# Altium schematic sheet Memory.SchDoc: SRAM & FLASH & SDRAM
size A4; DocumentNumber: MB1167; Revision: B.1; SheetNumber: 4; SheetTotal: 17; Project: STM327x6G-EVAL
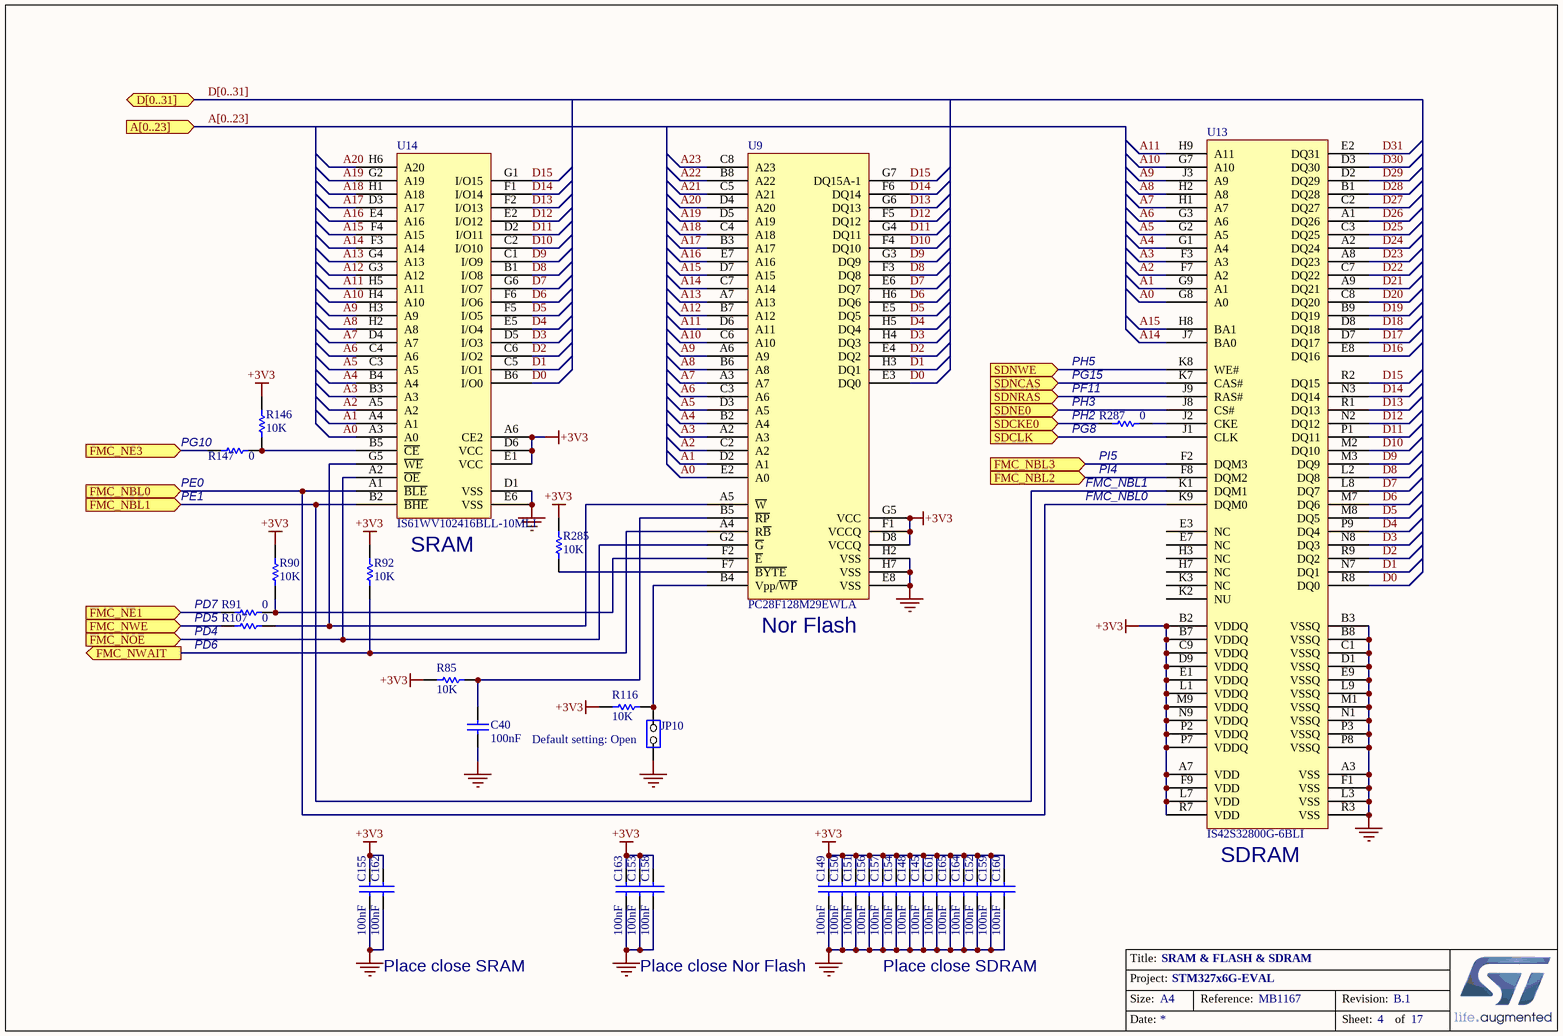
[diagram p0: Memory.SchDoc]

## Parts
C40  100nF  [0603C]
C145  100nF  [0603C]
C148  100nF  [0603C]
C149  100nF  [0603C]
C150  100nF  [0603C]
C151  100nF  [0603C]
C152  100nF  [0603C]
C153  100nF  [0603C]
C154  100nF  [0603C]
C155  100nF  [0603C]
C156  100nF  [0603C]
C157  100nF  [0603C]
C158  100nF  [0603C]
C159  100nF  [0603C]
C160  100nF  [0603C]
C161  100nF  [0603C]
C162  100nF  [0603C]
C163  100nF  [0603C]
C164  100nF  [0603C]
C165  100nF  [0603C]
JP10  (no value)  [SIP2]
R85  10K  [0603R]
R90  10K  [0603R]
R91  0  [0603R]
R92  10K  [0603R]
R107  0  [0603R]
R116  10K  [0603R]
R146  10K  [0603R]
R147  0  [0603R]
R285  10K  [0603R]
R287  0  [0603R]
U9  PC28F128M29EWLA  [FBGA64_1_11X13]
U13  IS42S32800G-6BLI  [FBGA90_0R8_8X13]
U14  IS61WV102416BLL-10MLI  [BGA48_0R75_9X11]

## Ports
A[0..23] (in), D[0..31] (bidir), FMC_NBL0 (in), FMC_NBL1 (in), FMC_NBL2 (in), FMC_NBL3 (in), FMC_NE1 (in), FMC_NE3 (in), FMC_NOE (in), FMC_NWAIT (out), FMC_NWE (in), SDCKE0 (in), SDCLK (in), SDNCAS (in), SDNE0 (in), SDNRAS (in), SDNWE (in)

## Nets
+3V3: C145.1 C148.1 C149.1 C150.1 C151.1 C152.1 C153.1 C154.1 C155.1 C156.1 C157.1 C158.1 C159.1 C160.1 C161.1 C162.1 C163.1 C164.1 C165.1 R85.1 R90.2 R92.2 R116.2 R146.2 R285.2 U9.D8(VCCQ) U9.F1(VCCQ) U9.G5(VCC) U13.A7(VDD) U13.B2(VDDQ) U13.B7(VDDQ) U13.C9(VDDQ) U13.D9(VDDQ) U13.E1(VDDQ) U13.F9(VDD) U13.L1(VDDQ) U13.L7(VDD) U13.M9(VDDQ) U13.N9(VDDQ) U13.P2(VDDQ) U13.P7(VDDQ) U13.R7(VDD) U14.A6(CE2) U14.D6(VCC) U14.E1(VCC)
GND: C40.2 C145.2 C148.2 C149.2 C150.2 C151.2 C152.2 C153.2 C154.2 C155.2 C156.2 C157.2 C158.2 C159.2 C160.2 C161.2 C162.2 C163.2 C164.2 C165.2 JP10.1(COMMON) U9.E8(VSS) U9.H2(VSS) U9.H7(VSS) U13.A3(VSS) U13.B3(VSSQ) U13.B8(VSSQ) U13.C1(VSSQ) U13.D1(VSSQ) U13.E9(VSSQ) U13.F1(VSS) U13.L3(VSS) U13.L9(VSSQ) U13.M1(VSSQ) U13.N1(VSSQ) U13.P3(VSSQ) U13.P8(VSSQ) U13.R3(VSS) U14.D1(VSS) U14.E6(VSS)
A0: U9.E2(A0) U13.G8(A0) U14.A3(A0)
A1: U9.D2(A1) U13.G9(A1) U14.A4(A1)
A2: U9.C2(A2) U13.F7(A2) U14.A5(A2)
A3: U9.A2(A3) U13.F3(A3) U14.B3(A3)
A4: U9.B2(A4) U13.G1(A4) U14.B4(A4)
A5: U9.D3(A5) U13.G2(A5) U14.C3(A5)
A6: U9.C3(A6) U13.G3(A6) U14.C4(A6)
A7: U9.A3(A7) U13.H1(A7) U14.D4(A7)
A8: U9.B6(A8) U13.H2(A8) U14.H2(A8)
A9: U9.A6(A9) U13.J3(A9) U14.H3(A9)
A10: U9.C6(A10) U13.G7(A10) U14.H4(A10)
A11: U9.D6(A11) U13.H9(A11) U14.H5(A11)
A12: U9.B7(A12) U14.G3(A12)
A13: U9.A7(A13) U14.G4(A13)
A14: U9.C7(A14) U13.J7(BA0) U14.F3(A14)
A15: U9.D7(A15) U13.H8(BA1) U14.F4(A15)
A16: U9.E7(A16) U14.E4(A16)
A17: U9.B3(A17) U14.D3(A17)
A18: U9.C4(A18) U14.H1(A18)
A19: U9.D5(A19) U14.G2(A19)
A20: U9.D4(A20) U14.H6(A20)
A21: U9.C5(A21)
A22: U9.B8(A22)
A23: U9.C8(A23)
D0: U9.E3(DQ0) U13.R8(DQ0) U14.B6(I/O0)
D1: U9.H3(DQ1) U13.N7(DQ1) U14.C5(I/O1)
D2: U9.E4(DQ2) U13.R9(DQ2) U14.C6(I/O2)
D3: U9.H4(DQ3) U13.N8(DQ3) U14.D5(I/O3)
D4: U9.H5(DQ4) U13.P9(DQ4) U14.E5(I/O4)
D5: U9.E5(DQ5) U13.M8(DQ5) U14.F5(I/O5)
D6: U9.H6(DQ6) U13.M7(DQ6) U14.F6(I/O6)
D7: U9.E6(DQ7) U13.L8(DQ7) U14.G6(I/O7)
D8: U9.F3(DQ8) U13.L2(DQ8) U14.B1(I/O8)
D9: U9.G3(DQ9) U13.M3(DQ9) U14.C1(I/O9)
D10: U9.F4(DQ10) U13.M2(DQ10) U14.C2(I/O10)
D11: U9.G4(DQ11) U13.P1(DQ11) U14.D2(I/O11)
D12: U9.F5(DQ12) U13.N2(DQ12) U14.E2(I/O12)
D13: U9.G6(DQ13) U13.R1(DQ13) U14.F2(I/O13)
D14: U9.F6(DQ14) U13.N3(DQ14) U14.F1(I/O14)
D15: U9.G7(DQ15A-1) U13.R2(DQ15) U14.G1(I/O15)
D16: U13.E8(DQ16)
D17: U13.D7(DQ17)
D18: U13.D8(DQ18)
D19: U13.B9(DQ19)
D20: U13.C8(DQ20)
D21: U13.A9(DQ21)
D22: U13.C7(DQ22)
D23: U13.A8(DQ23)
D24: U13.A2(DQ24)
D25: U13.C3(DQ25)
D26: U13.A1(DQ26)
D27: U13.C2(DQ27)
D28: U13.B1(DQ28)
D29: U13.D2(DQ29)
D30: U13.D3(DQ30)
D31: U13.E2(DQ31)
FMC_NBL0: U13.K9(DQM0) U14.A1(~{BLE}) ; port FMC_NBL0
FMC_NBL1: U13.K1(DQM1) U14.B2(~{BHE}) ; port FMC_NBL1
FMC_NBL2: U13.F8(DQM2) ; port FMC_NBL2
FMC_NBL3: U13.F2(DQM3) ; port FMC_NBL3
FMC_NE1: R91.2 ; port FMC_NE1
FMC_NE3: R147.2 ; port FMC_NE3
FMC_NOE: U9.G2(~{G}) U14.A2(~{OE}) ; port FMC_NOE
FMC_NWAIT: R92.1 U9.A4(R~{B}) ; port FMC_NWAIT
FMC_NWE: R107.2 ; port FMC_NWE
SDCKE0: R287.2 ; port SDCKE0
SDCLK: U13.J1(CLK) ; port SDCLK
SDNCAS: U13.K7(CAS#) ; port SDNCAS
SDNE0: U13.J8(CS#) ; port SDNE0
SDNRAS: U13.J9(RAS#) ; port SDNRAS
SDNWE: U13.K8(WE#) ; port SDNWE
NetC40_1: C40.1 R85.2 U9.B5(~{RP})
NetJP10_2: JP10.2(NO) R116.1 U9.B4(Vpp/~{WP})
NetR90_1: R90.1 R91.1 U9.F2(~{E})
NetR107_1: R107.1 U9.A5(~{W}) U14.G5(~{WE})
NetR146_1: R146.1 R147.1 U14.B5(~{CE})
NetR285_1: R285.1 U9.F7(~{BYTE})
NetR287_1: R287.1 U13.J2(CKE)

Not connected (* = marked no-connect by the designer): U13 E3(NC) E7(NC) H3(NC) H7(NC) K2(NU) K3(NC)

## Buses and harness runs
bus A[0..23] = port A[0..23]
bus D[0..31] = port D[0..31]

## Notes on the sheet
- PH5
- (near R287) PG15
- (near R147) PG10
- (near R287) PF11
- (near R287) PH3
- (near R287) PH2
- (near R287) PG8
- (near R147) PE1
- (near R147) PE0
- FMC_NBL1
- FMC_NBL0
- (near R287) PI5
- (near R287) PI4
- SRAM
- PD5
- PD7
- PD6
- PD4
- (near U9) Nor Flash
- (near JP10) Default setting: Open
- (near U13) SDRAM
- Place close SRAM
- Place close Nor Flash
- Place close SDRAM

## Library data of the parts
C40 C145 C148-C165 = Cap: Capacitor; Value: 10nF
JP10 = JP2
R85 R90-R92 R107 R116 R146 R147 R285 R287 = Res1: Resistor; Value: 1K
U9 = M29W128FL70ZA6E
U13 = MT48LC4M32B2B5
